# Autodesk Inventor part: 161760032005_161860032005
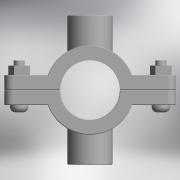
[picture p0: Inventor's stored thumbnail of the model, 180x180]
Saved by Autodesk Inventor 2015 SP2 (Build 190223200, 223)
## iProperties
Created: 2017-05
Part Number: 161760032005_161860032005
Material: Generic
Description: PLASSON DOUBLE SADDLE 32-1/2"
Document SubType Name: Modeling
Designer: KIM
Density: 1 g/cm^3
Appearance: Default
Author: KIM
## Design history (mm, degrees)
derived "16176.ipt"
feature "Solid1::16176.ipt"
feature "Solid2::16176.ipt"
tag "TaggingFeature1"
body "Solid1"
body "Solid2"
other parameters: "d0" = 48, "d1" = 92, "d2" = 16, "d3" = 32, "d5" = 0, "d6" = 4.6, "d7" = 92, "d8" = 0.1, "d10" = 0, "d11" = 0.32, "d20" = 0.32, "d23" = 0.32, "d37" = 8, "d38" = 24, "d39" = 0, "d40" = 3, "d41" = 5, "d42" = 0, "d43" = 6, "d44" = 3, "d45" = 0, "d46" = 0.32, "d52" = 18.631, "d53" = 18, "d54" = 0, "d55" = 16, "d57" = 0, "d58" = 34.56, "d60" = 0, "d66" = 0, "d68" = 24.2203, "d69" = 18.631, "d70" = 18, "d71" = 0, "d72" = 16, "d74" = 0, "d75" = 0.32, "d_" = 32, "B_" = 16, "G_" = 18.631, "L_" = 92, "l_2" = 18
